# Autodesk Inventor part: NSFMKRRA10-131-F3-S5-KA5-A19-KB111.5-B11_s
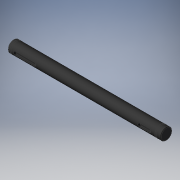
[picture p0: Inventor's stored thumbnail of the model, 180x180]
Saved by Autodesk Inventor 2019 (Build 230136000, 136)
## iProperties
Created: 2022-11
Part Number: NSFMKRRA10-131-F3-S5-KA5-A19-KB111.5-B11_s
Material: Generic
Catalog Web Link: www.cadenas.de
Description: NSFMKRR, SFMKRR, PSFMKRR, SSFMKRR, NSFHKRR, SFHKRR, PSFHKRR, SSFHKRR, NSFGKRR, SFGKRR, PSFGKRR, SSFGKRR, NSFMKRRA, SFMKRRA, PSFMKRRA, SSFMKRRA, NSFHKRRA, SFHKRR
Vendor: MISUMI
Document SubType Name: Modeling
Designer: psAdmin
Manufacturer: MISUMI
Mass: 10.1182 g
Surface Area: 43.8116 cm^2
Volume: 10.1182 cm^3
Density: 1 g/cm^3
Appearance: PSOLRGB-175-175-175
Category: PARTsolutions
Company: MISUMI
Title: NSFMKRRA10-131-F3-S5-KA5-A19-KB111.5-B11
Author: Cadenas PARTsolutions
Comments: Rotary Shafts - Retaining Ring Grooves on Both Ends with Keyway -
PSOL_IDENT_0: {$CADENAS_DATA/23d-libs/misumi/metric/11_rotary_shafts/11_components/psfgkrr/psfgkrr.prj},638 {VTYP=
PSOL_IDENT_1: 3D},{NB=NSFMKRRA10-131-F3-S5-KA5-A19-KB111.5-B11_s},{LINA=NSFMKRRA10-131-F3-S5-KA5-A19-KB111.5-B11},
PSOL_IDENT_2: {NN=NSFMKRR, SFMKRR, PSFMKRR, SSFMKRR, NSFHKRR, SFHKRR, PSFHKRR, SSFHKRR, NSFGKRR, SFGKRR, PSFGKRR,
PSOL_IDENT_3: SSFGKRR, NSFMKRRA, SFMKRRA, PSFMKRRA, SSFMKRRA, NSFHKRRA, SFHKRRA, PSFHKRRA, SSFHKRRA, NSFGKRRA, SFG
PSOL_IDENT_4: KRRA, PSFGKRRA, SSFGKRRA_shaft},{DATE=25.01.2022 23:09:52},{GEOMDATE=05.02.2021 08:15:17},{VERSION=}
PSOL_IDENT_5: ,{LINEID=30},{WBVAR=TS,TYS,MAT,ST,ALT1,L,F,S,NOK,KA,A,KB,B,KC,C,ALT3,FC,GALT3,WFC,J,WALT3,V,ALT4,SFC
PSOL_IDENT_6: ,SG,AG,ALT10,KWC,ALT11,WC,ALT5,UC,ALT7,SC,ALT32,CD},{WBNUMERIC=L,F,S,KA,A,KB,B,KC,C,FC,GALT3,WFC,J,W
PSOL_IDENT_7: ALT3,V,SFC,SG,AG,KWC,WC,UC,SC}  {NB=NSFMKRRA10-131-F3-S5-KA5-A19-KB111.5-B11_s},{LINA=NSFMKRRA10-131
PSOL_IDENT_8: -F3-S5-KA5-A19-KB111.5-B11},{KT=DUMMY},{PN=NSFMKRRA10-131-F3-S5-KA5-A19-KB111.5-B11},{TS=A},{TSALG=''
PSOL_IDENT_9: ,'Standard','A','Retaining Ring'},{TYS=M},{TYSALG= 'M','h9 (Cold-drawn)','H','h7 (Ground)','G','g6 (
PSOL_IDENT_10: Ground)' },{MAT=S45C},{MATALG= 'S45C','S45C Equivalent', 'SUS304','304 Stainless Steel' },{ST=},{STA
PSOL_IDENT_11: LG= '','-','BO','Black Oxide', 'ENP','Electroless Nickel Plating' },{TYPE=NSFMKRR},{D=10},{ALT1=},{L
PSOL_IDENT_12: KCMAX=799.9},{L=131.0},{LALG=[15:800/0.1]},{LMIN=15},{LMAX=800},{F=3.0},{FALG=[3:126/0.1]},{FMIN=3},
PSOL_IDENT_13: {FMAX1=122.8},{FMIN2=6.2},{FMAX2=126},{S=5.0},{SALG=[3:126/0.1]},{SMIN1=3},{SMAX1=121},{SMIN2=6.2},{
PSOL_IDENT_14: SMAX2=126},{DD=9.6},{MM=1.15},{MMALG=1.2},{MMJ=2},{NOK=2},{NOKALG= '1', 'with 1 Key Groove', '2'  , '
PSOL_IDENT_15: with 2 Key Grooves', '3'  , 'with 3 Key Grooves'},{CIFNOK1=0},{CIFNOK2=3},{CIFNOK3=0},{TOL1=0},{TOL2=
PSOL_IDENT_16: 3},{TOL3=0},{BB=3},{TT=1.8},{KA=5.0},{KAALG=[5:116/0.1]},{KAMIN1=0},{KAMIN2=5},{KAMIN3=129.2},{KAMAX
PSOL_IDENT_17: 1=-1000},{KAMAX2=116},{KAMAX3=-1000},{A=19.0},{AALG=[3:100/0.1]},{AMIN=3},{AMAX=100},{AMAX1=-1000},{
PSOL_IDENT_18: AMAX2=100},{AMAX3=-1000},{KAPN=-KA5-A19},{KB=111.5},{KBALG=[26:121/0.1]},{KBMIN1=26},{KBMIN2=26},{KB
PSOL_IDENT_19: MIN3=129.2},{KBMAX1=-1000},{KBMAX2=121},{KBMAX3=-1000},{B=11.0},{BALG=[3:12.5/0.1]},{BMIN=3},{BMAX=1
PSOL_IDENT_20: 2.5},{BMAX1=-1000},{BMAX2=12.5},{BMAX3=-1000},{KBPN=-KB111.5-B11},{KC=0.0},{KCALG=[0]},{KCMIN1=124.5
PSOL_IDENT_21: },{KCMIN2=124.5},{KCMIN3=129.2},{KCMAX1=-1000},{KCMAX2=-1000},{KCMAX3=-1000},{C=0.0},{CALG=0},{CMIN=
PSOL_IDENT_22: 3},{CMAX=-1000},{CMAX1=-1000},{CMAX2=-1000},{CMAX3=-1000},{CIFKA=5},{CIFKB=3},{CIFKC=3},{KCPN=},{ALT
PSOL_IDENT_23: 3=},{ALT3ALG= '', 'w/o Set Screw Flat','FC','with FC (Adds a Set Screw Flat)','WFC','with WFC (Adds
PSOL_IDENT_24: Two Set Screw Flats)','FCWFC','with FC + WFC (Adds Three Set Screw Flats)' },{ALT3PN=},{FC=0},{FCALG=
PSOL_IDENT_25: [0]},{FCMIN=0},{FCMAX=130},{GALT3=0},{GALT3ALG=[0]},{GALT3MIN=1},{GALT3MAX=70},{GALT3MAX2=70},{GALT3
PSOL_IDENT_26: MAX3=70},{WFC=0},{WFCALG=[0]},{WFCMIN=0},{WFCMIN2=2},{WFCMAX=127},{WFCMAX2=-3},{WFCMAX3=-4},{J=0},{J
PSOL_IDENT_27: ALG=[0]},{JMIN=1},{JMAX=70},{JMAX2=-2},{JMAX3=-5},{WALT3=0},{WALT3ALG=[0]},{WALT3MIN=0},{WALT3MIN2=1
PSOL_IDENT_28: 33},{WALT3MAX=128},{WALT3MAX2=128},{V=0},{VALG=[0]},{VMIN=1},{VMAX=70},{VMAX2=70},{CIFFC=0},{ALT4=},
PSOL_IDENT_29: {ALT4ALG= '', 'w/o SFC (2 Set Screw Flats (Angle Specified))', 'SFC'  , 'with SFC (2 Set Screw Flats
PSOL_IDENT_30: (Angle Specified))'},{ALT4PN=},{SFC=0},{SFCALG=[0]},{SFCMIN=0},{SFCMAX=130},{SG=0},{SGALG=[0]},{SGM
PSOL_IDENT_31: IN=1},{SGMAX=70},{AG=0},{AGALG=[0]},{H=0},{CIFSFC=0},{ALT10=},{ALT10ALG= '','Not applicable' },{KWC=
PSOL_IDENT_32: 0},{KWCALG=[0]},{KWCMIN=1},{KWCMAX=0},{WALT10=8},{ALT10PN=},{ALT11=},{ALT11ALG= '','Not applicable'
PSOL_IDENT_33: },{WC=0.0},{WCALG=[0]},{ALT11PN=},{ALT5=},{ALT5ALG= '', 'w/o UC (Slit Cam Groove)', 'UC', 'with UC (
PSOL_IDENT_34: Slit Cam Groove)'},{ALT5PN=},{UC=0},{UCALG=[0]},{UCMIN=1},{UCMAX=125},{DDALT5=0},{LL1=0},{ALT7=},{AL
PSOL_IDENT_35: T7ALG= '', 'w/o SC (Wrench Flats)', 'SC', 'with SC (Wrench Flats)'},{ALT7PN=},{SC=0},{SCALG=[0]},{SC
PSOL_IDENT_36: MIN=0},{SCMAX=123},{LL2=0},{LL2ALG=8},{WALT7=0},{CIFSC=0},{ALT32=},{ALT32ALG= '','w/o CD (Changes Pa
PSOL_IDENT_37: rt D Chamfering)','CD','with CD (Changes Part D Chamfering)' },{CD=},{CDALG= '','N/A' },{CD3D=0.5},{
PSOL_IDENT_38: ALT32PN=},{CIF323R=0},{CIF323L=0},{CIF324R=0},{CIF324L=0},{CIF3210=0},{CIF32F=0},{CIF32S=0},{ERRORPN=
PSOL_IDENT_39: },{ERRORKGALT3=OK},{ERRORKGALT4=OK},{ERRORKGALT5=OK},{ERRORKGALT7=OK},{ERRORKGALT10=OK},{ERRORRALT3=
PSOL_IDENT_40: OK},{ERRORRALT4=NG},{ERRORRALT5=NG},{ERRORRALT7=NG},{ERRORRALT10=OK},{ERRORALT34=OK},{ERRORALT35=OK}
PSOL_IDENT_41: ,{ERRORALT37=OK},{ERRORALT310=OK},{ERRORALT45=OK},{ERRORALT47=OK},{ERRORALT410=OK},{ERRORALT57=OK},{
PSOL_IDENT_42: ERRORALT510=OK},{ERRORALT710=OK},{PCUT3D=0},{QCUT3D=0},{TTALT2=1.8},{BBALT2=3}
NB: NSFMKRRA10-131-F3-S5-KA5-A19-KB111.5-B11_s
NN: NSFMKRR, SFMKRR, PSFMKRR, SSFMKRR, NSFHKRR, SFHKRR, PSFHKRR, SSFHKRR, NSFGKRR, SFGKRR, PSFGKRR, SSFGKRR, NSFMKRRA, SFMKRRA, PSFMKRRA, SSFMKRRA, NSFHKRRA, SFHKRR
NT: Rotary Shafts - Retaining Ring Grooves on Both Ends with Keyway -
NBSYN: $PN._s
LINA: NSFMKRRA10-131-F3-S5-KA5-A19-KB111.5-B11
CATALOG: Misumi
PN: NSFMKRRA10-131-F3-S5-KA5-A19-KB111.5-B11
TS: Retaining Ring
TYS: h9 (Cold-drawn)
MAT: S45C Equivalent
ST: -
D: 10
ALT1: w/o LKC (Changes L Tolerance)
L: 131
F: 3
S: 5
DD: 9.6
MM: 1.15
NOK: with 2 Key Grooves
KA: 5
A: 19
KB: 111.5
B: 11
KC: 0
C: 0
ALT3: w/o Set Screw Flat
FC: 0
GALT3: 0
WFC: 0
J: 0
WALT3: 0
V: 0
ALT4: w/o SFC (2 Set Screw Flats (Angle Specified))
SFC: 0
SG: 0
AG: 0
H: 0
ALT10: Not applicable
KWC: 0
ALT11: Not applicable
WC: 0
ALT5: w/o UC (Slit Cam Groove)
UC: 0
DDALT5: 0
LL1: 0
ALT7: w/o SC (Wrench Flats)
SC: 0
LL2: 0
WALT7: 0
ALT32: w/o CD (Changes Part D Chamfering)
CD: N/A
SUPPLIER: MISUMI
ARTICLENO: NSFMKRRA10-131-F3-S5-KA5-A19-KB111.5-B11_s
BOMINFO: NSFMKRRA10-131-F3-S5-KA5-A19-KB111.5-B11
CREATOR: CADENAS GmbH
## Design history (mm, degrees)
sketch "Sketch_1"
  geometry: L1 (-131, 0)-(0, 0); L2 (0, 0)-(0, -4.5); L3 (0, -4.5)-(-0.5, -5); L4 (-0.5, -5)-(-130.5, -5); L5 (-130.5, -5)-(-131, -4.5); L6 (-131, -4.5)-(-131, 0); L7 (-131, 0)-(0, 0)
  constraints: 14 end point
revolve "Revolution1" sketch "Sketch_1" stored, may be unused: angle "d0" = 360 deg
sketch "Sketch_27"
  geometry: L1 (131, 0)-(-131, 0); L2 (1.85, 9.6)-(1.85, 4.8); L3 (1.85, 4.8)-(3, 4.8); L4 (3, 4.8)-(3, 9.6); L5 (3, 9.6)-(1.85, 9.6)
  constraints: 10 end point
revolve "Revolution2" sketch "Sketch_27" stored, may be unused: angle "d1" = 360 deg
sketch "Sketch_39"
  geometry: L1 (131, 0)-(-131, 0); L2 (126, 9.6)-(126, 4.8); L3 (126, 4.8)-(127.15, 4.8); L4 (127.15, 4.8)-(127.15, 9.6); L5 (127.15, 9.6)-(126, 9.6)
  constraints: 10 end point
revolve "Revolution3" sketch "Sketch_39" stored, may be unused: angle "d2" = 360 deg
sketch "_____7"
  geometry: L1 (6.5, -1.5)-(22.5, -1.5); L2 (22.5, 1.5)-(6.5, 1.5); A1 r 1.5 centre (6.5, 0) between (6.5, 1.5) and (6.5, -1.5); A2 r 1.5 centre (22.5, 0) between (22.5, -1.5) and (22.5, 1.5)
  constraints: 4 end point, 4 point on circle, 2 centre point
extrude "Extrusion1" cut sketch "_____7" distance "d3" = 1.8; taper "d4" = 0 deg
sketch "_____10"
  geometry: L1 (113, -1.5)-(121, -1.5); L2 (121, 1.5)-(113, 1.5); A1 r 1.5 centre (113, 0) between (113, 1.5) and (113, -1.5); A2 r 1.5 centre (121, 0) between (121, -1.5) and (121, 1.5)
  constraints: 4 end point, 4 point on circle, 2 centre point
extrude "Extrusion2" cut sketch "_____10" distance "d5" = 1.8; taper "d6" = 0 deg
node "to_rring_1_XY"
node "to_rring_1_YZ"
node "to_rring_1_ZX"
node "to_rring_1_X"
node "to_rring_1_Y"
node "to_rring_1_Z"
node "to_rring_1_Center"
node "to_rring_2_XY"
node "to_rring_2_YZ"
node "to_rring_2_ZX"
node "to_rring_2_X"
node "to_rring_2_Y"
node "to_rring_2_Z"
node "to_rring_2_Center"
body "Solid1"
